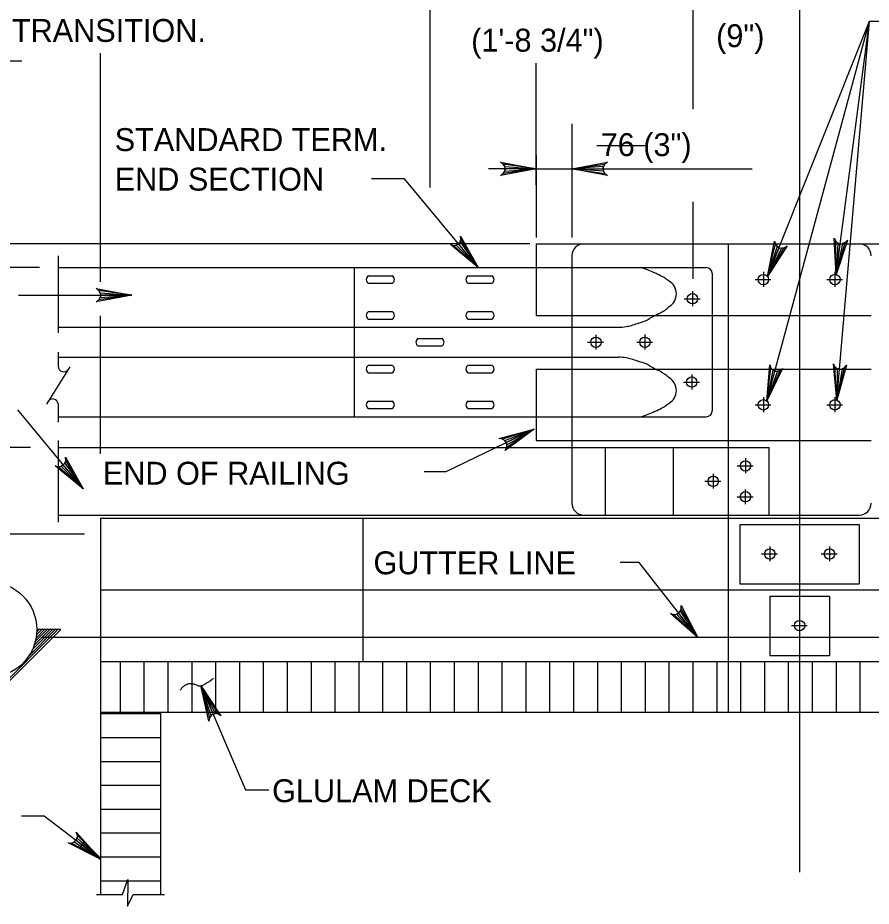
# Model space of a CAD drawing. Extents: x 179 to 454, y -271 to 54.
# Drawn here: x 365.182 to 369.653, y -16.519 to -11.865 of the extents above; entities that cross this region are included whole.
import ezdxf

# ---------------------------------------------------------------- set-up
doc = ezdxf.new("R2010")
doc.units = 0
for name, color, linetype in [('Level 2', 7, 'Continuous'), ('Level 3', 7, 'Continuous'), ('Level 41', 7, 'Continuous'), ('Level 63', 7, 'Continuous')]:
    doc.layers.add(name, color=color, linetype=linetype)

# ---------------------------------------------------------------- blocks, each defined once
blk = doc.blocks.new('$X5430')
at = {"layer": 'Level 63'}
for p, q in [((5.4191, 3.4375), (5.6806, 3.4375)), ((5.4191, 3.3333), (5.6806, 3.3333)), ((5.4191, 3.2292), (5.6806, 3.2292)), ((5.4191, 3.125), (5.6806, 3.125)), ((5.4191, 3.0208), (5.6806, 3.0208)), ((5.4191, 2.9167), (5.6806, 2.9167)), ((5.4191, 2.8125), (5.6806, 2.8125)), ((5.4191, 2.7083), (5.6806, 2.7083))]:
    blk.add_line(p, q, dxfattribs=at)

msp = doc.modelspace()

# ---------------------------------------------------------------- linework, layer by layer
at = {"layer": 'Level 2'}
for p, q in [((367.8979, -13.0486), (369.9448, -13.0486)), ((368.9031, -13.0486), (368.9031, -15.5017)), ((365.3935, -13.1114), (365.3935, -13.5143)), ((368.0854, -13.1111), (368.0854, -13.9547)), ((365.3936, -13.1736), (366.9454, -13.1736)), ((366.9454, -13.1736), (366.9454, -13.9547)), ((366.9454, -13.1736), (368.7892, -13.1736)), ((367.019, -13.2165), (367.144, -13.2165)), ((367.5412, -13.2165), (367.6662, -13.2165)), ((367.8979, -13.1736), (367.8979, -13.4236)), ((368.8204, -13.2048), (368.8204, -13.9236)), ((369.0881, -13.1963), (369.0881, -13.2744)), ((369.4632, -13.1963), (369.4632, -13.2744)), ((367.019, -13.2556), (367.144, -13.2556)), ((367.5412, -13.2556), (367.6662, -13.2556)), ((369.0447, -13.2361), (369.1279, -13.2361)), ((369.4198, -13.2361), (369.5031, -13.2361)), ((368.7163, -13.2968), (368.7163, -13.3748)), ((368.6728, -13.3367), (368.7562, -13.3367)), ((367.019, -13.404), (367.144, -13.404)), ((367.019, -13.4431), (367.144, -13.4431)), ((367.5412, -13.404), (367.6662, -13.404)), ((367.5412, -13.4431), (367.6662, -13.4431)), ((367.8979, -13.4236), (369.6531, -13.4236)), ((365.3936, -13.4861), (368.3271, -13.4861)), ((368.2109, -13.5252), (368.2109, -13.6032)), ((368.4679, -13.5243), (368.4679, -13.6023)), ((367.2796, -13.5447), (367.4046, -13.5447)), ((367.2796, -13.5837), (367.4046, -13.5837)), ((368.1675, -13.5642), (368.2508, -13.5642)), ((368.4245, -13.5642), (368.5077, -13.5642)), ((365.3935, -13.6165), (365.3935, -13.6911)), ((365.3936, -13.6422), (368.3271, -13.6422)), ((365.455, -13.6925), (365.3322, -13.8881)), ((367.019, -13.6852), (367.144, -13.6852)), ((367.019, -13.7243), (367.144, -13.7243)), ((367.5412, -13.6852), (367.6662, -13.6852)), ((367.5412, -13.7243), (367.6662, -13.7243)), ((367.8979, -13.7047), (369.6531, -13.7047)), ((367.8979, -13.7047), (367.8979, -13.9547)), ((368.6697, -13.7729), (368.7529, -13.7729)), ((368.7131, -13.7331), (368.7131, -13.8111)), ((369.0881, -13.8524), (369.0881, -13.9304)), ((369.4632, -13.8524), (369.4632, -13.9304)), ((365.3935, -13.8878), (365.3935, -13.9834)), ((367.019, -13.8727), (367.144, -13.8727)), ((367.019, -13.9118), (367.144, -13.9118)), ((367.5412, -13.8727), (367.6662, -13.8727)), ((367.5412, -13.9118), (367.6662, -13.9118)), ((369.0447, -13.8922), (369.1279, -13.8922)), ((369.4198, -13.8922), (369.5031, -13.8922)), ((365.3936, -13.9547), (368.7892, -13.9547)), ((368.0854, -13.9547), (368.0854, -14.4072)), ((367.8879, -14.0192), (367.4251, -14.2425)), ((365.3935, -14.0797), (365.3935, -14.506)), ((367.8979, -14.0797), (368.0854, -14.0797)), ((368.0854, -14.0797), (369.6531, -14.0797)), ((365.3936, -14.116), (369.1191, -14.116)), ((368.9943, -14.1723), (368.9943, -14.2503)), ((368.9509, -14.2122), (369.0342, -14.2122)), ((367.4251, -14.2425), (367.3107, -14.2425)), ((368.8252, -14.253), (368.8252, -14.331)), ((368.7817, -14.2928), (368.8651, -14.2928)), ((368.9509, -14.3736), (369.0342, -14.3736)), ((368.9943, -14.4134), (368.9943, -14.3354)), ((365.3936, -14.4697), (369.5906, -14.4697)), ((368.9031, -14.4697), (368.9031, -14.4861)), ((365.6163, -14.4861), (371.4434, -14.4861)), ((365.6163, -14.4861), (365.6163, -14.861)), ((366.9894, -14.4861), (366.9894, -15.236)), ((368.9656, -14.5197), (368.9656, -14.8297)), ((368.9656, -14.5197), (369.5906, -14.5197)), ((369.5906, -14.5197), (369.5906, -14.8297)), ((369.1218, -14.6337), (369.1218, -14.7117)), ((369.4343, -14.6337), (369.4343, -14.7117)), ((369.0784, -14.6735), (369.1617, -14.6735)), ((369.3909, -14.6735), (369.4742, -14.6735)), ((368.9656, -14.8297), (369.5906, -14.8297)), ((365.6163, -14.861), (371.4434, -14.861)), ((369.1218, -14.8947), (369.1218, -15.2047)), ((369.1218, -14.8947), (369.4343, -14.8947)), ((369.4343, -14.8947), (369.4343, -15.2047)), ((369.2781, -15.0087), (369.2781, -15.0867)), ((369.2347, -15.0485), (369.318, -15.0485)), ((369.1218, -15.2047), (369.4343, -15.2047)), ((365.6163, -15.236), (371.4434, -15.236)), ((365.6163, -15.5017), (371.4434, -15.5017)), ((365.6163, -15.5017), (365.6163, -16.4573)), ((365.9302, -15.5017), (365.9302, -16.4573)), ((365.3215, -16.0474), (365.2015, -16.0474)), ((365.6163, -16.2717), (365.3215, -16.0474))]:
    msp.add_line(p, q, dxfattribs=at)
msp.add_lwpolyline([(365.5299, -16.1808), (365.5068, -16.2135), (365.6163, -16.2665)], close=True, dxfattribs=at)
for centre in [(369.088, -13.2361), (369.4631, -13.2361), (368.7162, -13.3367), (368.2108, -13.5642), (368.4678, -13.5642), (368.713, -13.773), (369.088, -13.8923), (369.4631, -13.8923), (368.9943, -14.2122), (368.8251, -14.2929), (368.9943, -14.3736), (369.1218, -14.6736), (369.4343, -14.6736), (369.278, -15.0486)]:
    msp.add_circle(centre, 0.0273, dxfattribs=at)
for centre, radius, start, end in [((368.1478, -13.1111), 0.0625, 90, 180), ((367.0306, -13.2361), 0.0228, 120.8559, 239.1441), ((367.1323, -13.2361), 0.0228, 300.8559, 59.1441), ((367.5528, -13.2361), 0.0228, 120.8559, 239.1441), ((367.6545, -13.2361), 0.0228, 300.8559, 59.1441), ((368.1938, -13.9961), 0.8602, 71.5066, 72.9766), ((368.4161, -13.3314), 0.1594, 68.0907, 71.5066), ((366.4329, -18.2624), 5.4742, 67.6851, 68.0907), ((368.321, -13.6622), 0.5016, 66.3453, 67.6851), ((368.4402, -13.3899), 0.2044, 63.4251, 66.3453), ((367.3283, -15.6128), 2.6898, 62.6202, 63.4251), ((368.7891, -13.2048), 0.0312, 0, 90), ((368.5282, -13.2961), 0.0808, 54.6771, 62.6202), ((368.3589, -13.5349), 0.3735, 50.9849, 54.6771), ((368.5549, -13.3115), 0.0775, 301.3851, 59.6468), ((352.6959, 15.7881), 33.224, 298.47252, 298.525), ((368.5178, -13.322), 0.092, 298.525, 306.8818), ((368.3222, -13.0613), 0.4179, 306.8818, 310.7993), ((367.0306, -13.4236), 0.0228, 120.8559, 239.1441), ((367.1323, -13.4236), 0.0228, 300.8559, 59.1441), ((367.5528, -13.4236), 0.0228, 120.8559, 239.1441), ((367.6545, -13.4236), 0.0228, 300.8559, 59.1441), ((368.4545, -13.3991), 0.0545, 290.2329, 298.3215), ((367.6196, -11.85), 1.8143, 298.3215, 298.7501), ((373.1737, -21.9738), 9.733, 118.56505, 118.75012), ((373.6299, -22.8118), 10.6871, 118.47252, 118.56505), ((368.3074, -13.061), 0.4255, 272.6429, 278.367), ((368.3428, -13.3014), 0.1825, 278.367, 287.1115), ((366.1081, -6.0426), 7.7775, 287.11147, 287.36106), ((368.3495, -13.2121), 0.2658, 287.3611, 288.7111), ((367.9417, -12.0079), 1.5372, 288.7111, 290.2329), ((367.2912, -13.5642), 0.0228, 120.8559, 239.1441), ((367.3928, -13.5642), 0.0228, 300.8559, 59.1441), ((368.3074, -14.0674), 0.4255, 81.633, 87.3571), ((368.3428, -13.827), 0.1825, 72.8885, 81.633), ((366.1081, -21.0858), 7.7775, 72.63894, 72.88853), ((368.3495, -13.9163), 0.2658, 71.2889, 72.6389), ((367.9417, -15.1205), 1.5372, 69.7671, 71.2889), ((368.4545, -13.7293), 0.0545, 61.6785, 69.7671), ((367.6196, -15.2784), 1.8143, 61.2499, 61.6785), ((365.4224, -13.6903), 0.0289, 180, 330), ((367.0306, -13.7048), 0.0228, 120.8559, 239.1441), ((367.1323, -13.7048), 0.0228, 300.8559, 59.1441), ((367.5528, -13.7048), 0.0228, 120.8559, 239.1441), ((367.6545, -13.7048), 0.0228, 300.8559, 59.1441), ((373.1737, -5.1546), 9.733, 241.24988, 241.43495), ((373.6299, -4.3166), 10.6871, 241.43495, 241.52748), ((352.6959, -42.9165), 33.224, 61.475, 61.52748), ((368.5178, -13.8064), 0.092, 53.1182, 61.475), ((368.3222, -14.0671), 0.4179, 49.2007, 53.1182), ((368.5549, -13.8169), 0.0775, 300.3532, 58.6149), ((365.3648, -13.8904), 0.0289, 5.3286, 147.8672), ((367.0306, -13.8923), 0.0228, 120.8559, 239.1441), ((367.1323, -13.8923), 0.0228, 300.8559, 59.1441), ((367.5528, -13.8923), 0.0228, 120.8559, 239.1441), ((367.6545, -13.8923), 0.0228, 300.8559, 59.1441), ((367.3283, -11.5156), 2.6898, 296.5749, 297.3798), ((368.5282, -13.8323), 0.0808, 297.3798, 305.3229), ((368.3589, -13.5935), 0.3735, 305.3229, 309.0151), ((368.1938, -13.1323), 0.8602, 287.0234, 288.4934), ((368.4161, -13.797), 0.1594, 288.4934, 291.9093), ((366.4329, -8.8659), 5.4742, 291.9093, 292.3149), ((368.321, -13.4662), 0.5016, 292.3149, 293.6547), ((368.4402, -13.7384), 0.2044, 293.6547, 296.5749), ((368.7891, -13.9236), 0.0312, 270, 0), ((368.1478, -14.4073), 0.0625, 180, 270), ((369.5905, -14.4073), 0.0625, 270, 0)]:
    msp.add_arc(centre, radius, start, end, dxfattribs=at)
at = {"layer": 'Level 3'}
for p, q in [((369.2781, -9.9667), (369.2781, -16.3403)), ((367.342, -12.7536), (367.342, -11.6451)), ((368.7183, -11.7564), (368.7183, -12.3434)), ((369.1064, -13.872), (369.6448, -11.8824)), ((369.1104, -13.2203), (369.6448, -11.8824)), ((369.4694, -13.2094), (369.6448, -11.8824)), ((369.4733, -13.8669), (369.6448, -11.8824)), ((369.6448, -11.8824), (369.7648, -11.8824)), ((365.6163, -13.2478), (365.6163, -12.0503)), ((365.2042, -12.092), (364.7042, -12.092)), ((367.8979, -12.7394), (367.8979, -12.1021)), ((368.0854, -12.4202), (368.0854, -13.016)), ((367.8979, -12.584), (367.8979, -13.016)), ((367.881, -12.6559), (367.6485, -12.6559)), ((367.8097, -12.6559), (369.0302, -12.6559)), ((367.2074, -12.7081), (367.0362, -12.7081)), ((367.5947, -13.1736), (367.2074, -12.7081)), ((368.7183, -12.8288), (368.7183, -13.2318)), ((367.8648, -13.0486), (362.9008, -13.0486)), ((367.8979, -13.0486), (367.8979, -13.1736)), ((365.2957, -13.1736), (363.628, -13.1736)), ((365.1863, -13.318), (365.7795, -13.318)), ((365.6163, -14.1495), (365.6163, -13.4265)), ((365.5244, -14.3327), (365.1825, -13.9182)), ((367.8979, -13.9547), (367.8979, -14.0797)), ((365.25, -14.116), (364.0865, -14.116)), ((368.2611, -14.4697), (368.2611, -14.116)), ((368.6178, -14.4697), (368.6178, -14.116)), ((369.1191, -14.4697), (369.1191, -14.116)), ((365.5322, -14.5695), (365.0322, -14.5695)), ((368.4372, -14.7177), (368.3382, -14.7177)), ((368.7444, -15.111), (368.4372, -14.7177)), ((365.6163, -14.861), (365.6163, -15.236)), ((365.0251, -15.4374), (365.393, -15.0695)), ((365.0322, -15.4445), (365.4072, -15.0695)), ((365.2402, -15.2082), (365.3789, -15.0695)), ((365.2584, -15.1758), (365.3648, -15.0695)), ((365.2682, -15.1519), (365.3506, -15.0695)), ((365.2743, -15.1317), (365.3365, -15.0695)), ((365.2783, -15.1136), (365.3223, -15.0695)), ((365.2807, -15.097), (365.3082, -15.0695)), ((365.2819, -15.0817), (365.294, -15.0695)), ((365.4072, -15.0695), (365.2822, -15.0695)), ((370.5075, -15.111), (365.3121, -15.111)), ((365.6163, -15.236), (365.6163, -15.5017)), ((365.7203, -15.5017), (365.7203, -15.236)), ((365.8453, -15.5017), (365.8453, -15.236)), ((365.9703, -15.5017), (365.9703, -15.236)), ((366.0953, -15.5017), (366.0953, -15.236)), ((366.2203, -15.5017), (366.2203, -15.236)), ((366.3453, -15.5017), (366.3453, -15.236)), ((366.4703, -15.5017), (366.4703, -15.236)), ((366.5953, -15.5017), (366.5953, -15.236)), ((366.7203, -15.5017), (366.7203, -15.236)), ((366.8453, -15.5017), (366.8453, -15.236)), ((366.9703, -15.5017), (366.9703, -15.236)), ((367.0953, -15.5017), (367.0953, -15.236)), ((367.2203, -15.5017), (367.2203, -15.236)), ((367.3453, -15.5017), (367.3453, -15.236)), ((367.4703, -15.5017), (367.4703, -15.236)), ((367.5953, -15.5017), (367.5953, -15.236)), ((367.7203, -15.5017), (367.7203, -15.236)), ((367.8453, -15.5017), (367.8453, -15.236)), ((367.9703, -15.5017), (367.9703, -15.236)), ((368.0953, -15.5017), (368.0953, -15.236)), ((368.2203, -15.5017), (368.2203, -15.236)), ((368.3453, -15.5017), (368.3453, -15.236)), ((368.4703, -15.5017), (368.4703, -15.236)), ((368.5953, -15.5017), (368.5953, -15.236)), ((368.7203, -15.5017), (368.7203, -15.236)), ((368.8453, -15.5017), (368.8453, -15.236)), ((368.9703, -15.5017), (368.9703, -15.236)), ((369.0953, -15.5017), (369.0953, -15.236)), ((369.2203, -15.5017), (369.2203, -15.236)), ((369.3453, -15.5017), (369.3453, -15.236)), ((369.4703, -15.5017), (369.4703, -15.236)), ((369.5953, -15.5017), (369.5953, -15.236)), ((366.1417, -15.3632), (366.3745, -15.9092)), ((366.3745, -15.9092), (366.4983, -15.9092)), ((365.7308, -16.4573), (365.7593, -16.3792)), ((365.7593, -16.3792), (365.757, -16.5186)), ((365.5944, -16.4573), (365.7308, -16.4573)), ((365.757, -16.5186), (365.7877, -16.4573)), ((365.7877, -16.4573), (365.9504, -16.4573))]:
    msp.add_line(p, q, dxfattribs=at)
for points in [[(367.8979, -12.6559), (367.7115, -12.6908), (367.7258, -12.6809), (367.7332, -12.6684), (367.7354, -12.6559), (367.7332, -12.6434), (367.7258, -12.6309), (367.7115, -12.621), (367.8979, -12.6559), (367.7258, -12.6309), (367.7332, -12.6434), (367.8979, -12.6559), (367.7354, -12.6559), (367.7332, -12.6684), (367.8979, -12.6559), (367.7258, -12.6809)], [(368.0854, -12.6559), (368.2718, -12.621), (368.2575, -12.6309), (368.2501, -12.6434), (368.2479, -12.6559), (368.2501, -12.6684), (368.2575, -12.6809), (368.2718, -12.6908), (368.0854, -12.6559), (368.2575, -12.6809), (368.2501, -12.6684), (368.0854, -12.6559), (368.2479, -12.6559), (368.2501, -12.6434), (368.0854, -12.6559), (368.2575, -12.6309)], [(367.5947, -13.1736), (367.4486, -13.0527), (367.4654, -13.0573), (367.4797, -13.055), (367.4907, -13.0487), (367.499, -13.039), (367.5038, -13.0253), (367.5023, -13.0079), (367.5947, -13.1736), (367.5038, -13.0253), (367.499, -13.039), (367.5947, -13.1736), (367.4907, -13.0487), (367.4797, -13.055), (367.5947, -13.1736), (367.4654, -13.0573)], [(369.4694, -13.2094), (369.4592, -13.02), (369.4672, -13.0356), (369.4786, -13.0446), (369.4907, -13.0483), (369.5034, -13.0478), (369.5168, -13.0422), (369.5285, -13.0292), (369.4694, -13.2094), (369.5168, -13.0422), (369.5034, -13.0478), (369.4694, -13.2094), (369.4907, -13.0483), (369.4786, -13.0446), (369.4694, -13.2094), (369.4672, -13.0356)], [(369.1104, -13.2203), (369.1471, -13.0343), (369.151, -13.0512), (369.1599, -13.0628), (369.1707, -13.0694), (369.1831, -13.0721), (369.1974, -13.0698), (369.212, -13.0602), (369.1104, -13.2203), (369.1974, -13.0698), (369.1831, -13.0721), (369.1104, -13.2203), (369.1707, -13.0694), (369.1599, -13.0628), (369.1104, -13.2203), (369.151, -13.0512)], [(365.7795, -13.3179), (365.5931, -13.3529), (365.6075, -13.3429), (365.6149, -13.3304), (365.617, -13.3179), (365.6149, -13.3054), (365.6075, -13.2929), (365.5931, -13.283), (365.7795, -13.3179), (365.6075, -13.2929), (365.6149, -13.3054), (365.7795, -13.3179), (365.617, -13.3179), (365.6149, -13.3304), (365.7795, -13.3179), (365.6075, -13.3429)], [(369.4733, -13.8669), (369.4546, -13.6782), (369.4632, -13.6933), (369.4751, -13.7018), (369.4873, -13.705), (369.5, -13.704), (369.5131, -13.6977), (369.5242, -13.6842), (369.4733, -13.8669), (369.5131, -13.6977), (369.5, -13.704), (369.4733, -13.8669), (369.4873, -13.705), (369.4751, -13.7018), (369.4733, -13.8669), (369.4632, -13.6933)], [(369.1064, -13.872), (369.1213, -13.6829), (369.1273, -13.6994), (369.1373, -13.7098), (369.1488, -13.7152), (369.1615, -13.7163), (369.1755, -13.7124), (369.1888, -13.7012), (369.1064, -13.872), (369.1755, -13.7124), (369.1615, -13.7163), (369.1064, -13.872), (369.1488, -13.7152), (369.1373, -13.7098), (369.1064, -13.872), (369.1273, -13.6994)], [(367.8879, -14.0192), (367.7352, -14.1318), (367.7438, -14.1165), (367.7451, -14.102), (367.7416, -14.0898), (367.7342, -14.0795), (367.7221, -14.0715), (367.7048, -14.0687), (367.8879, -14.0192), (367.7221, -14.0715), (367.7342, -14.0795), (367.8879, -14.0192), (367.7416, -14.0898), (367.7451, -14.102), (367.8879, -14.0192), (367.7438, -14.1165)], [(365.5244, -14.3327), (365.3788, -14.2111), (365.3957, -14.2158), (365.41, -14.2137), (365.421, -14.2073), (365.4292, -14.1977), (365.4342, -14.1841), (365.4327, -14.1667), (365.5244, -14.3327), (365.4342, -14.1841), (365.4292, -14.1977), (365.5244, -14.3327), (365.421, -14.2073), (365.41, -14.2137), (365.5244, -14.3327), (365.3957, -14.2158)], [(368.7444, -15.111), (368.6021, -14.9857), (368.6187, -14.9908), (368.6332, -14.989), (368.6443, -14.9829), (368.6529, -14.9736), (368.6582, -14.96), (368.6572, -14.9426), (368.7444, -15.111), (368.6582, -14.96), (368.6529, -14.9736), (368.7444, -15.111), (368.6443, -14.9829), (368.6332, -14.989), (368.7444, -15.111), (368.6187, -14.9908)], [(366.1417, -15.3632), (366.2469, -15.521), (366.2322, -15.5117), (366.2177, -15.5098), (366.2054, -15.5127), (366.1947, -15.5196), (366.1862, -15.5313), (366.1827, -15.5484), (366.1417, -15.3632), (366.1862, -15.5313), (366.1947, -15.5196), (366.1417, -15.3632), (366.2054, -15.5127), (366.2177, -15.5098), (366.1417, -15.3632), (366.2322, -15.5117)], [(365.6163, -16.2717), (365.4468, -16.1867), (365.4642, -16.1874), (365.4778, -16.1819), (365.487, -16.1732), (365.4928, -16.1621), (365.4945, -16.1476), (365.4891, -16.131), (365.6163, -16.2717), (365.4945, -16.1476), (365.4928, -16.1621), (365.6163, -16.2717), (365.487, -16.1732), (365.4778, -16.1819), (365.6163, -16.2717), (365.4642, -16.1874)]]:
    msp.add_lwpolyline(points, dxfattribs=at)
msp.add_circle((365.0321, -15.0695), 0.25, dxfattribs=at)
for centre, radius, start, end in [((369.5905, -13.1111), 0.0625, 0, 90), ((366.1486, -15.5182), 0.1803, 116.5624, 121.4049), ((366.078, -15.377), 0.0224, 102.8072, 116.5624), ((366.0817, -15.3934), 0.0393, 90, 102.8072), ((366.0817, -15.5371), 0.183, 84.0775, 90), ((366.0953, -15.4069), 0.0521, 61.2712, 84.0775), ((366.1242, -15.2915), 0.074, 288.433, 300.6618), ((365.9412, -14.9829), 0.4328, 300.6618, 302.0024), ((365.3813, -14.0868), 1.4894, 302.0024, 302.725), ((366.0775, -15.1702), 0.2016, 302.725, 305.5345), ((365.8688, -14.8781), 0.5606, 305.5345, 307.2191), ((366.1018, -15.4245), 0.0773, 138.8108, 152.4815), ((366.0796, -15.4051), 0.0478, 121.4049, 138.8108), ((366.1325, -15.339), 0.0254, 241.2712, 274.1568), ((366.1304, -15.3101), 0.0544, 274.1568, 288.433)]:
    msp.add_arc(centre, radius, start, end, dxfattribs=at)
at = {"layer": 'Level 41'}
msp.add_line((368.2154, -12.5335), (368.4802, -12.5335), dxfattribs=at)

# ---------------------------------------------------------------- block references
at = {"layer": 'Level 2', "xscale": 1.1999976, "yscale": 1.1999976}
msp.add_blockref('$X5430', (359.1134, -19.6347), dxfattribs=at)

# ---------------------------------------------------------------- texts
at = {"layer": 'Level 3'}
for s, p in [('   GUIDE RAIL TRANSITION.', (364.0638, -11.9912)), ('(9")', (368.8407, -12.0188)), ('(1\'-8 3/4")', (367.5576, -12.0422)), ('STANDARD TERM.', (365.6902, -12.5629)), ('76 (3")', (368.2359, -12.5895)), ('END SECTION', (365.6902, -12.7702)), ('END OF RAILING', (365.6281, -14.3104)), ('GUTTER LINE', (367.0456, -14.7798)), ('GLULAM DECK', (366.5148, -15.9736))]:
    msp.add_text(s, height=0.12, dxfattribs=at).set_placement(p)

doc.saveas('drawing.dxf')
